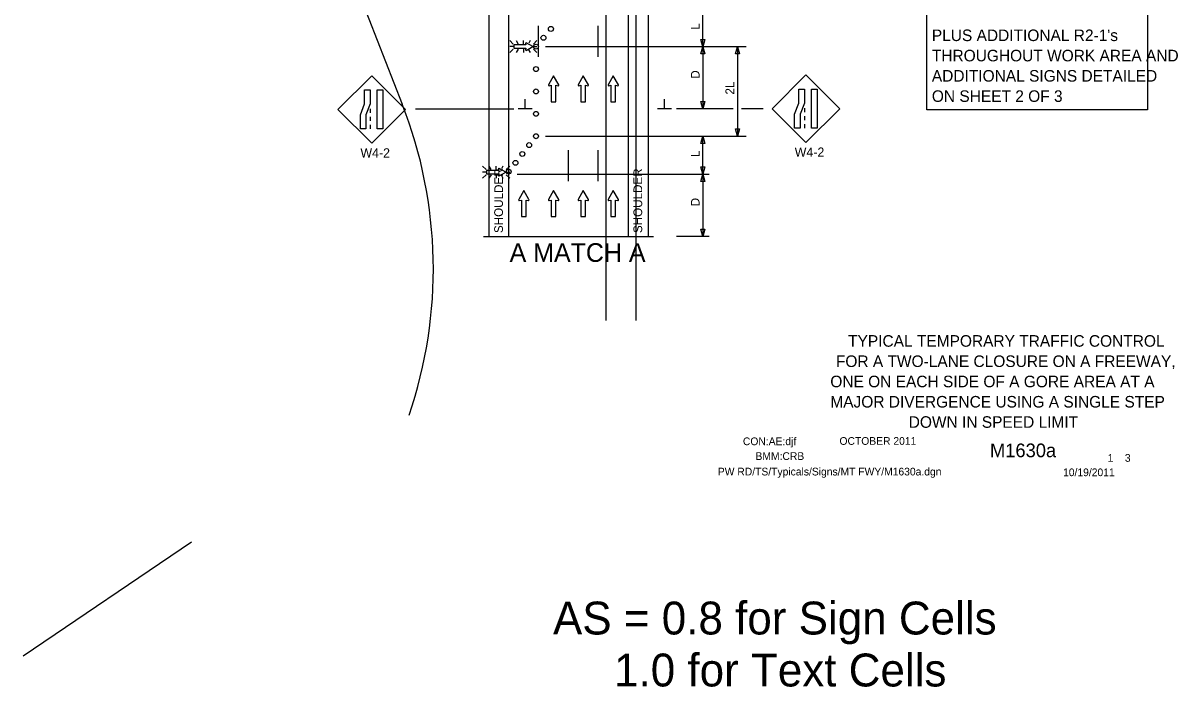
# Model space of a CAD drawing. Extents: x 16512 to 19512, y 5761 to 6974.
# Drawn here: x 16512 to 17440, y 5764 to 6297 of the extents above; entities that cross this region are included whole.
import ezdxf

# ---------------------------------------------------------------- set-up
doc = ezdxf.new("R2010")
doc.units = 0
for name, color, linetype in [('ALI_LEGAL_EX', 7, 'Continuous'), ('BORDER', 7, 'Continuous'), ('BORDER_SIGNAL_WO', 7, 'Continuous'), ('MT_SCRATCH_LEVEL_E', 7, 'Continuous'), ('PAVT_EDGE_EX', 7, 'Continuous'), ('TRAFFIC_SIGNS_PR', 7, 'Continuous'), ('TYPICAL_TEXT_DIMEN_EX', 7, 'Continuous'), ('TYPICAL_TEXT_DIMEN_PR', 7, 'Continuous')]:
    doc.layers.add(name, color=color, linetype=linetype)

msp = doc.modelspace()

# ---------------------------------------------------------------- linework, layer by layer
at = {"layer": 'ALI_LEGAL_EX'}
for p, q in [((16980.68, 6974.12), (16980.68, 6155.98)), ((17004.68, 6974.12), (17004.68, 6155.98)), ((16980.68, 6922.21), (16980.68, 6058.3)), ((17004.68, 6922.21), (17004.68, 6058.3)), ((16594.98, 6800.51), (16817, 6232.14))]:
    msp.add_line(p, q, dxfattribs=at)
for points in [[(16926.45, 6270.33), (16926.45, 6295.33)], [(16974.45, 6270.33), (16974.45, 6295.33)], [(16950.45, 6170.33), (16950.45, 6195.33)], [(16974.45, 6170.33), (16974.45, 6195.33)]]:
    msp.add_lwpolyline(points, dxfattribs=at)
msp.add_arc((16477.95, 6099.7), 364, 341.14594, 21.33672, dxfattribs=at)
at = {"layer": 'BORDER'}
msp.add_line((17289.25, 6011.25), (17289.25, 6011.25), dxfattribs=at)
msp.add_line((17289.25, 6011.25), (17289.25, 6011.25), dxfattribs=at)
at = {"layer": 'MT_SCRATCH_LEVEL_E'}
for p, q in [((16938.54, 6255.03), (16934.43, 6247.79)), ((16942.69, 6247.79), (16938.54, 6255.03)), ((16962.45, 6255.03), (16958.33, 6247.79)), ((16966.59, 6247.79), (16962.45, 6255.03)), ((16986.5, 6255.03), (16982.39, 6247.79)), ((16990.65, 6247.79), (16986.5, 6255.03)), ((16934.91, 6247.11), (16936.69, 6247.43)), ((16936.69, 6247.43), (16936.69, 6234.17)), ((16940.43, 6234.17), (16940.43, 6247.43)), ((16940.43, 6247.43), (16942.21, 6247.11)), ((16958.82, 6247.11), (16960.59, 6247.43)), ((16960.59, 6247.43), (16960.59, 6234.17)), ((16964.34, 6234.17), (16964.34, 6247.43)), ((16964.34, 6247.43), (16966.11, 6247.11)), ((16982.87, 6247.11), (16984.65, 6247.43)), ((16984.65, 6247.43), (16984.65, 6234.17)), ((16988.39, 6234.17), (16988.39, 6247.43)), ((16988.39, 6247.43), (16990.17, 6247.11)), ((16936.69, 6234.17), (16940.43, 6234.17)), ((16960.59, 6234.17), (16964.34, 6234.17)), ((16984.65, 6234.17), (16988.39, 6234.17)), ((16914.64, 6162.72), (16910.53, 6155.48)), ((16918.78, 6155.48), (16914.64, 6162.72)), ((16938.54, 6162.72), (16934.43, 6155.48)), ((16942.69, 6155.48), (16938.54, 6162.72)), ((16962.45, 6162.72), (16958.33, 6155.48)), ((16966.59, 6155.48), (16962.45, 6162.72)), ((16986.5, 6162.72), (16982.39, 6155.48)), ((16990.65, 6155.48), (16986.5, 6162.72)), ((16911.01, 6154.79), (16912.79, 6155.11)), ((16912.79, 6155.11), (16912.79, 6141.85)), ((16916.53, 6141.85), (16916.53, 6155.11)), ((16916.53, 6155.11), (16918.31, 6154.79)), ((16934.91, 6154.79), (16936.69, 6155.11)), ((16936.69, 6155.11), (16936.69, 6141.85)), ((16940.43, 6141.85), (16940.43, 6155.11)), ((16940.43, 6155.11), (16942.21, 6154.79)), ((16958.82, 6154.79), (16960.59, 6155.11)), ((16960.59, 6155.11), (16960.59, 6141.85)), ((16964.34, 6141.85), (16964.34, 6155.11)), ((16964.34, 6155.11), (16966.11, 6154.79)), ((16982.87, 6154.79), (16984.65, 6155.11)), ((16984.65, 6155.11), (16984.65, 6141.85)), ((16988.39, 6141.85), (16988.39, 6155.11)), ((16988.39, 6155.11), (16990.17, 6154.79)), ((16912.79, 6141.85), (16916.53, 6141.85)), ((16936.69, 6141.85), (16940.43, 6141.85)), ((16960.59, 6141.85), (16964.34, 6141.85)), ((16984.65, 6141.85), (16988.39, 6141.85))]:
    msp.add_line(p, q, dxfattribs=at)
for centre, start, end in [((16934.84, 6247.57), 150.42484, 279.96381), ((16942.28, 6247.57), 260.03619, 29.77312), ((16958.74, 6247.57), 150.42484, 279.96381), ((16966.18, 6247.57), 260.03619, 29.77312), ((16982.8, 6247.57), 150.42484, 279.96381), ((16990.24, 6247.57), 260.03619, 29.77312), ((16910.93, 6155.25), 150.42484, 279.96381), ((16918.38, 6155.25), 260.03619, 29.77312), ((16934.84, 6155.25), 150.42484, 279.96381), ((16942.28, 6155.25), 260.03619, 29.77312), ((16958.74, 6155.25), 150.42484, 279.96381), ((16966.18, 6155.25), 260.03619, 29.77312), ((16982.8, 6155.25), 150.42484, 279.96381), ((16990.24, 6155.25), 260.03619, 29.77312)]:
    msp.add_arc(centre, 0.463, start, end, dxfattribs=at)
at = {"layer": 'PAVT_EDGE_EX'}
for p, q in [((16886.45, 6480.53), (16886.45, 6125.9)), ((16902.45, 6480.53), (16902.45, 6125.9)), ((16998.45, 6480.53), (16998.45, 6125.9)), ((17014.45, 6480.53), (17014.45, 6125.9))]:
    msp.add_line(p, q, dxfattribs=at)
at = {"layer": 'TRAFFIC_SIGNS_PR'}
for p, q in [((16906.22, 6280.57), (16903.4, 6283.39)), ((16908.52, 6283.39), (16910.15, 6280.57)), ((16914.31, 6280.57), (16914.31, 6283.39)), ((16919.78, 6283.39), (16918.57, 6281.3)), ((16925.21, 6283.39), (16922.39, 6280.57)), ((16906.22, 6278.54), (16903.4, 6278.54)), ((16906.22, 6276.51), (16903.4, 6273.69)), ((16910.17, 6276.51), (16908.54, 6273.69)), ((16914.31, 6276.51), (16914.31, 6273.69)), ((16918.49, 6275.87), (16919.75, 6273.69)), ((16922.39, 6278.54), (16925.21, 6278.54)), ((16925.21, 6273.69), (16922.39, 6276.51)), ((16792.4, 6255.09), (16765.25, 6227.93)), ((16819.55, 6227.93), (16792.4, 6255.09)), ((17141.36, 6255.7), (17114.21, 6228.54)), ((17168.51, 6228.54), (17141.36, 6255.7)), ((16765.25, 6227.93), (16792.4, 6200.78)), ((16791.15, 6228.43), (16791.15, 6225.23)), ((16792.4, 6200.78), (16819.55, 6227.93)), ((17114.21, 6228.54), (17141.36, 6201.39)), ((17140.11, 6229.03), (17140.11, 6225.83)), ((17141.36, 6201.39), (17168.51, 6228.54)), ((16791.15, 6222.03), (16791.15, 6218.83)), ((17140.11, 6222.63), (17140.11, 6219.43)), ((16791.15, 6215.63), (16791.15, 6212.43)), ((17140.11, 6216.23), (17140.11, 6213.03)), ((16884.35, 6179.62), (16881.53, 6182.44)), ((16886.65, 6182.44), (16888.27, 6179.62)), ((16892.43, 6179.62), (16892.43, 6182.44)), ((16897.9, 6182.44), (16896.69, 6180.35)), ((16903.34, 6182.44), (16900.52, 6179.62)), ((16884.35, 6177.59), (16881.53, 6177.59)), ((16884.35, 6175.56), (16881.53, 6172.74)), ((16888.3, 6175.56), (16886.67, 6172.74)), ((16892.43, 6175.56), (16892.43, 6172.74)), ((16896.62, 6174.92), (16897.88, 6172.74)), ((16900.52, 6177.59), (16903.34, 6177.59)), ((16903.34, 6172.74), (16900.52, 6175.56))]:
    msp.add_line(p, q, dxfattribs=at)
for points in [[(16916.13, 6281.22), (16916.36, 6279.93), (16906.64, 6279.93), (16906.64, 6277.18), (16916.36, 6277.18), (16916.13, 6275.88)], [(16916.63, 6275.53), (16921.94, 6278.54), (16916.63, 6281.58)], [(16894.26, 6180.27), (16894.49, 6178.97), (16884.77, 6178.97), (16884.77, 6176.23), (16894.49, 6176.23), (16894.26, 6174.93)], [(16894.76, 6174.57), (16900.07, 6177.59), (16894.76, 6180.63)]]:
    msp.add_lwpolyline(points, dxfattribs=at)
for points in [[(16791.15, 6243.67), (16791.15, 6232.49), (16787.81, 6223.61), (16787.81, 6212.43), (16783.32, 6212.43), (16783.32, 6223.61), (16786.66, 6232.49), (16786.66, 6243.67)], [(16801.29, 6243.67), (16801.29, 6212.43), (16796.8, 6212.43), (16796.8, 6243.67)], [(17140.11, 6244.28), (17140.11, 6233.1), (17136.77, 6224.22), (17136.77, 6213.03), (17132.27, 6213.03), (17132.27, 6224.22), (17135.62, 6233.1), (17135.62, 6244.28)], [(17150.25, 6244.28), (17150.25, 6213.03), (17145.76, 6213.03), (17145.76, 6244.28)]]:
    msp.add_lwpolyline(points, close=True, dxfattribs=at)
for centre in [(16936.44, 6292.75), (16930.44, 6285.61), (16924.44, 6278.47), (16924.44, 6260.47), (16924.44, 6242.47), (16924.44, 6224.47), (16924.44, 6206.47), (16918.95, 6199.34), (16913.45, 6192.21), (16902.46, 6177.96), (16907.95, 6185.08)]:
    msp.add_circle(centre, 2, dxfattribs=at)
for centre, start, end in [((16916.47, 6281.28), 61.48329, 189.95933), ((16916.47, 6275.82), 170.73078, 298.89165), ((16894.6, 6180.33), 61.48329, 189.95933), ((16894.6, 6174.87), 170.73078, 298.89165)]:
    msp.add_arc(centre, 0.341, start, end, dxfattribs=at)
at = {"layer": 'TYPICAL_TEXT_DIMEN_EX'}
msp.add_lwpolyline([(17238.46, 6313.09), (17415.73, 6313.09), (17415.73, 6227.77), (17238.46, 6227.77)], close=True, dxfattribs=at)
at = {"layer": 'TYPICAL_TEXT_DIMEN_PR'}
for p, q in [((17058.45, 6278.47), (17058.45, 6307.03)), ((17058.45, 6278.47), (17056.88, 6284.33)), ((17056.88, 6284.33), (17058.45, 6284.33)), ((17058.45, 6284.33), (17060.02, 6284.33)), ((17060.02, 6284.33), (17058.45, 6278.47)), ((17093.24, 6278.47), (16931.95, 6278.47)), ((17056.88, 6272.61), (17058.45, 6278.47)), ((17058.45, 6272.61), (17056.88, 6272.61)), ((17058.45, 6278.47), (17058.45, 6228.47)), ((17058.45, 6278.47), (17060.02, 6272.61)), ((17060.02, 6272.61), (17058.45, 6272.61)), ((17084.68, 6272.61), (17086.25, 6278.47)), ((17086.25, 6272.61), (17084.68, 6272.61)), ((17086.25, 6278.47), (17087.82, 6272.61)), ((17086.25, 6278.47), (17086.25, 6206.47)), ((17087.82, 6272.61), (17086.25, 6272.61)), ((16915.73, 6228.47), (16915.73, 6236.25)), ((17027.57, 6228.47), (17027.57, 6236.25)), ((16827.54, 6228.47), (16906.74, 6228.47)), ((16921.36, 6228.47), (16910.11, 6228.47)), ((17033.2, 6228.47), (17021.95, 6228.47)), ((17082.83, 6228.47), (17037.45, 6228.47)), ((17058.45, 6228.47), (17056.88, 6234.33)), ((17056.88, 6234.33), (17058.45, 6234.33)), ((17058.45, 6234.33), (17060.02, 6234.33)), ((17060.02, 6234.33), (17058.45, 6228.47)), ((17106.9, 6228.47), (17089.54, 6228.47)), ((17086.25, 6206.47), (17084.68, 6212.33)), ((17084.68, 6212.33), (17086.25, 6212.33)), ((17086.25, 6212.33), (17087.82, 6212.33)), ((17087.82, 6212.33), (17086.25, 6206.47)), ((16931.95, 6206.47), (17093.24, 6206.47)), ((17056.88, 6200.61), (17058.45, 6206.47)), ((17058.45, 6200.61), (17056.88, 6200.61)), ((17058.45, 6175.9), (17058.45, 6206.47)), ((17058.45, 6206.47), (17060.02, 6200.61)), ((17060.02, 6200.61), (17058.45, 6200.61)), ((17058.45, 6175.9), (17056.88, 6181.77)), ((17056.88, 6181.77), (17058.45, 6181.77)), ((17058.45, 6181.77), (17060.02, 6181.77)), ((17060.02, 6181.77), (17058.45, 6175.9)), ((16909.4, 6175.9), (17063.45, 6175.9)), ((17056.88, 6170.04), (17058.45, 6175.9)), ((17058.45, 6175.9), (17058.45, 6125.9)), ((17058.45, 6175.9), (17060.02, 6170.04)), ((17058.45, 6170.04), (17056.88, 6170.04)), ((17060.02, 6170.04), (17058.45, 6170.04)), ((16882.15, 6125.9), (17018.8, 6125.9)), ((17063.45, 6125.9), (17037.45, 6125.9)), ((17058.45, 6125.9), (17056.88, 6131.77)), ((17056.88, 6131.77), (17058.45, 6131.77)), ((17058.45, 6131.77), (17060.02, 6131.77)), ((17060.02, 6131.77), (17058.45, 6125.9)), ((16647.75, 5880), (16512.32, 5788.38))]:
    msp.add_line(p, q, dxfattribs=at)

# ---------------------------------------------------------------- texts
at = {"layer": 'BORDER'}
for s, p in [('TYPICAL TEMPORARY TRAFFIC CONTROL', (17175.21, 6037.21)), ('FOR A TWO-LANE CLOSURE ON A FREEWAY,', (17165.41, 6020.91)), ('ONE ON EACH SIDE OF A GORE AREA AT A ', (17160.92, 6004.62)), ('MAJOR DIVERGENCE USING A SINGLE STEP ', (17160.92, 5988.32)), ('DOWN IN SPEED LIMIT', (17223.92, 5972.02))]:
    msp.add_text(s, height=9.3, dxfattribs=at).set_placement(p)
at = {"layer": 'BORDER_SIGNAL_WO'}
for s, height, p in [('CON:AE:djf  ', 6.2, (17090.69, 5958.06)), ('    OCTOBER 2011    ', 6.2, (17159.08, 5958.34)), ('    M1630a   ', 11, (17272.86, 5948.38)), ('BMM:CRB   ', 6.2, (17100.81, 5946.17)), (' 1    3 ', 6.2, (17381.45, 5944.7)), ('PW RD/TS/Typicals/Signs/MT FWY/M1630a.dgn      ', 6.2, (17070.55, 5933.71)), ('10/19/2011    ', 6.2, (17347.93, 5933.13)), ('AS = 0.8 for Sign Cells', 26.4241, (16938.08, 5805.84)), ('     1.0 for Text Cells', 26.4241, (16938.08, 5764.05))]:
    msp.add_text(s, height=height, dxfattribs=at).set_placement(p)
at = {"layer": 'TRAFFIC_SIGNS_PR'}
for p in [(16783.36, 6189.34), (17132.32, 6189.95)]:
    msp.add_text('W4-2', height=7.44, dxfattribs=at).set_placement(p)
at = {"layer": 'TYPICAL_TEXT_DIMEN_EX'}
for s, p in [("PLUS ADDITIONAL R2-1's", (17242.51, 6282.97)), ('THROUGHOUT WORK AREA AND', (17242.51, 6266.67)), ('ADDITIONAL SIGNS DETAILED', (17242.51, 6250.37)), ('ON SHEET 2 OF 3', (17242.51, 6234.07))]:
    msp.add_text(s, height=9.3, dxfattribs=at).set_placement(p)
at = {"layer": 'TYPICAL_TEXT_DIMEN_PR'}
for s, p in [('L', (17055.98, 6292.11)), ('D', (17055.89, 6252.69)), ('2L', (17083.69, 6239.97)), ('L', (17055.89, 6189.76)), ('SHOULDER', (16897.88, 6128.61)), ('SHOULDER', (17009.74, 6128.61)), ('D', (17055.89, 6150.12))]:
    msp.add_text(s, height=7, rotation=90, dxfattribs=at).set_placement(p)
msp.add_text('A MATCH A', height=15, dxfattribs=at).set_placement((16903.24, 6105.44))

doc.saveas('drawing.dxf')
